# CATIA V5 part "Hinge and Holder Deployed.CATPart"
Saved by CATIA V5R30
Part number: 1
Material "Aluminium": density 2710 kg/m3, Young's modulus 7e+10 Pa, Poisson ratio 0.346, thermal expansion 2.36e-05 1/K
Bounding box of the stored display mesh (mm): x -9.5 to 9.5, y -8.725 to 18.341, z -0.505 to 29.547
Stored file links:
  P:\GOOD Deployed hinge and holder CATPart.CATPart
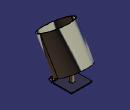
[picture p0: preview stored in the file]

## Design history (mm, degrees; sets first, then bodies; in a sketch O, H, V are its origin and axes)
Body1 (main body), material "Aluminium"
  Sketch1 on yz-plane, origin (0, 0, 0), H (0, 1, 0), V (0, 0, 1)
    point P1 (15, 0)
    line L1 (15, 0) -> (2.6419, 0)
    line L2 (2.2705, 1.3508) -> (12.8911, 7.6694)
    point P2 (12.8911, 7.6694)
    arc A1 centre (2.6419, 0.7265) radius 0.7265 from (2.6419, 0) to (2.2705, 1.3508) cw
    distance P1 V = 15
    angle L2 H = 30.75
    distance O P2 = 15
    radius A1 = 0.7265
    coincidence: P1 H, L1 O, L2 O
    horizontal: L1 H
    tangency: A1 L1, A1 L2
  Plane1: type Normal, Curve Sketch1, RefPoint Sketch1.P1, Ratio 0
  Sketch2 on Plane1, origin (0, 15, 0), H (-1, 0, 0), V (0, 0, 1)
    line L1 (6.25, 0) -> (6.25, -0.5053)
    line L2 (6.25, -0.5053) -> (-6.25, -0.5053)
    line L3 (-6.25, -0.5053) -> (-6.25, 0)
    line L4 (-6.25, 0) -> (6.25, 0)
    distance L1 L3 = 12.5
    vertical: L1 V, L3 V
    horizontal: L2 H, L4 H
    equidistance: L1 L3 O
  Rib1: profile Sketch2, centre curve Sketch1
  Sketch3 on face of Rib1, origin (0, -0.5452, 0.2636), H (1, 0, 0), V (0, 0.8594, 0.5113)
    circle A1 centre (0, 12.4757) radius 9.5
    point P1 (0, 12.4757)
    reference projected line E1 (6.25, 2.9757) -> (-6.25, 2.9757) from edge [face of Rib1 | face of Rib1]
    radius A1 = 9.5
    distance A1 E1 = 0
    coincidence: P1 V
  Pad1: profile Sketch3, direction (0, -0.5113, 0.8594), length 1
  Sketch4 on end face of Pad1, origin (0, -1.6302, 0.7817), H (1, 0, 0), V (0, 0.8594, 0.5113)
    circle A1 centre (0, 13.1433) radius 9.5
    point P1 (0, 13.1433)
    reference projected circle E1 centre (0, 13.1433) radius 9.5 from edge [face of Pad1 from Sketch3.A1 | end face of Pad1]
    circle A2 centre (0, 13.1433) radius 9
    radius A1 = 9.5
    radius A2 = 9
    coincidence: P1 V
    concentricity: A1 E1
  Pad2: profile Sketch4, direction (0, -0.5113, 0.8594), length 20
  Sketch5 on face of Rib1, origin (0, 0, 0), H (1, 0, 0), V (0, 1, 0)
    circle A1 centre (0, 8.9267) radius 1.3689
    point P1 (0, 8.9267)
    coincidence: P1 V
  Pad3: profile Sketch5, direction (0, 0, 1), up to the existing solid (limit type 2)
  Sketch6 on face of Rib1, origin (6.25, 0, 0), H (0, 1, 0), V (0, 0, 1)
    circle A1 centre (2.6476, 0.7263) radius 1.2325
    point P2 (1.76, 1.5814)
    point P3 (1.4979, 0.2821)
    point P4 (2.7558, -0.5015)
    radius A1 = 1.2325
    coincidence: A1 P2, A1 P3, A1 P4
  Pad4: profile Sketch6, direction (-1, 0, 0), up to face of Rib1
  Sketch7 on face of Rib1, origin (6.25, 0, 0), H (0, 1, 0), V (0, 0, 1)
    circle A1 centre (2.6476, 0.7263) radius 0.8088
  Pocket1: profile Sketch7, direction (-1, 0, 0), up to face of Rib1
